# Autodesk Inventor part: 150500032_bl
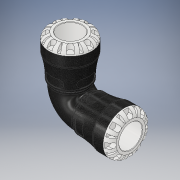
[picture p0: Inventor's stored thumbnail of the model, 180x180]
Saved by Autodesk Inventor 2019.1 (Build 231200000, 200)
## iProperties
Created: 2016-12
Part Number: 150500032_bl
Material: PVC-Piping
Description: PLASSON G-PLASS 90°  ELBOW 32X32
Document SubType Name: Modeling
Designer: KIM
Mass: 664.223 g
Surface Area: 733.008 cm^2
Volume: 474.445 cm^3
Density: 1.4 g/cm^3
Appearance: Black Cast
Author: KIM
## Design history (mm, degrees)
derived "150500.ipt"
feature "Solid1::150500.ipt" dims "ScaleForDerivedMember" = 10
tag "TaggingFeature1"
body "Solid1"
other parameters: "d1" = 23.52 [user parameter], "d2" = 32 [user parameter], "d4" = 58 [user parameter], "d8" = 49.3 [user parameter], "d13" = 7.2 [user parameter], "d14" = 7.2 [user parameter], "d15" = 0 [user parameter], "d17" = 360 deg [user parameter], "d19" = 8 deg [user parameter], "d20" = 0.64 [user parameter], "d21" = 0.64 [user parameter], "d22" = 8 deg [user parameter], "d24" = 0 [user parameter], "d26" = 360 deg [user parameter], "d33" = 5.8 [user parameter], "d43" = 45.24 [user parameter], "d51" = 0.58 [user parameter], "d54" = 11.2 [user parameter], "d55" = 7.04 [user parameter], "d57" = 14.112 [user parameter], "d58" = 0 [user parameter], "d74" = 0 [user parameter], "d77" = 2.66667 [user parameter], "d78" = 56 [user parameter], "d82" = 0.64 [user parameter], "d115" = 360 deg [user parameter], "d207" = 90 deg [user parameter], "d228" = 9.52 [user parameter], "d247" = 1.16 [user parameter], "d248" = 3.36 [user parameter], "d268" = 27.115 [user parameter], "d269" = 3.36 [user parameter], "d270" = 83 [user parameter], "d272" = 90 deg [user parameter], "d274" = 0 [user parameter], "d275" = 0 [user parameter], "d_" = 32 [user parameter], "E_" = 58 [user parameter], "l_" = 56 [user parameter], "A_" = 83 [user parameter], "d9" = 9 [user parameter], "d11" = 58 [user parameter]
